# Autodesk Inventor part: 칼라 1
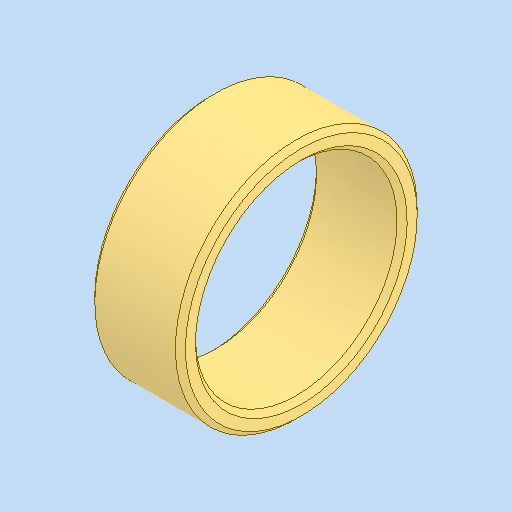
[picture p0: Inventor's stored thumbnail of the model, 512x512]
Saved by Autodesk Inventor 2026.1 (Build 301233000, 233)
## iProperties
Created: 2025-11
Part Number: 칼라 1
Material: 강철, 연강
Document SubType Name: Modeling
Designer: PC-30
Density: 7.85 g/cm^3
Appearance: 기본값
Author: jhkim
Sending System: Autodesk Inventor 2026
Preprocessor: ST-DEVELOPER v20.1
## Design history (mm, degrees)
feature "솔리드1"
node "솔리드2"
